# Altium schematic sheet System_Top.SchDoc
size 431 x 279 mm; SheetNumber: 1; SheetTotal: 4; PageSetup: Record=PageOptions¦CenterHorizontal=True¦CenterVertical=True¦PrintScale=1.01¦XCorrection=1.00¦YCorrection=1.00¦PrintKind=1¦BorderSize=5000000¦LeftOffset=0¦BottomOffset=0¦Orientation=2¦PaperLength=1000¦PaperWidth=1000¦Scale=100¦PaperSource=7¦PrintQuality=600¦MediaType=1¦DitherType=10¦PaperKind=A3¦PrintScaleMode=1; ENG_APP_DATE: --/--/--; DSN_APP_DATE: --/--/--; CHK_APP_DATE: --/--/--
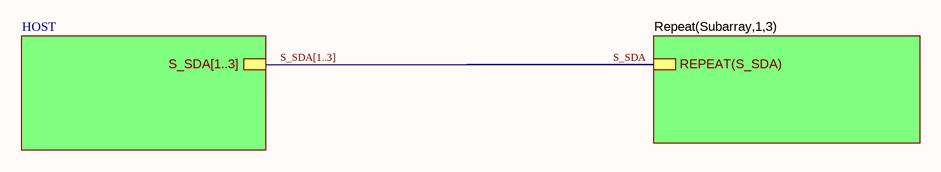
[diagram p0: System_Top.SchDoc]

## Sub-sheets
HOST = HOST.SchDoc: S_SDA[1..3]
Repeat(Subarray,1,3) = Subarray.SchDoc: REPEAT(S_SDA)

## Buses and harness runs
bus S_SDA[1..3] = sheet HOST/S_SDA[1..3]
